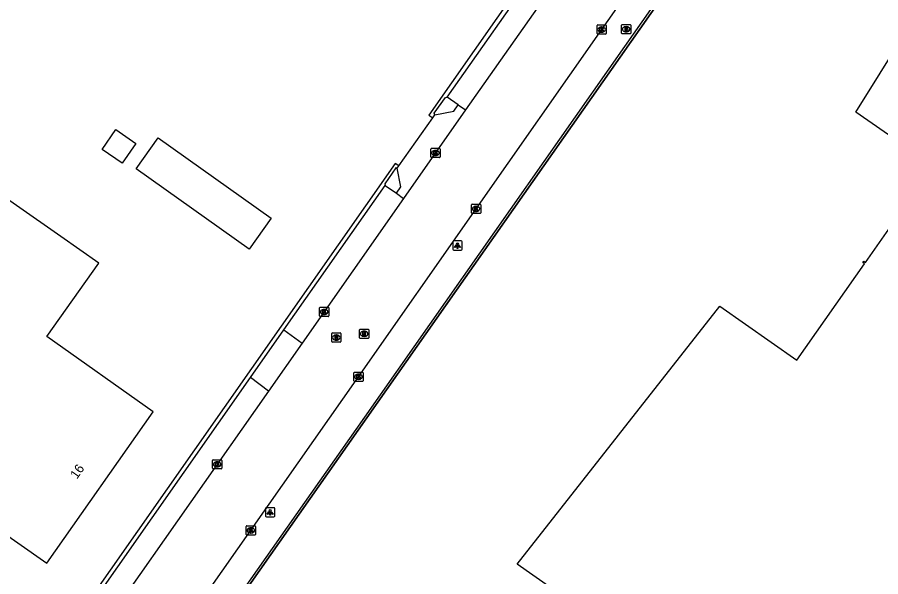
# Model space of a CAD drawing. Extents: x 155018 to 156648, y 383980 to 385733.
# Drawn here: x 155571.4 to 155664.5, y 384753.9 to 384814.2 of the extents above; entities that cross this region are included whole.
import ezdxf

# ---------------------------------------------------------------- set-up
doc = ezdxf.new("R2010")
doc.units = 0
for name, color, linetype in [('IMGEO_Brandkraan', 7, 'Continuous'), ('IMGEO_Groenvoorziening', 7, 'Continuous'), ('IMGEO_Hek', 7, 'Continuous'), ('IMGEO_Kolk', 7, 'Continuous'), ('IMGEO_Lichtpunt', 7, 'Continuous'), ('IMGEO_Pand', 7, 'Continuous'), ('IMGEO_Pand_nummerreeks', 7, 'Continuous'), ('IMGEO_Parkeervlak_open', 7, 'Continuous'), ('IMGEO_Rijbaan_lokaal_gesloten', 7, 'Continuous'), ('IMGEO_Rioolput', 7, 'Continuous'), ('IMGEO_Voetpad_open', 7, 'Continuous')]:
    doc.layers.add(name, color=color, linetype=linetype)

msp = doc.modelspace()

# ---------------------------------------------------------------- linework, layer by layer
at = {"layer": 'IMGEO_Brandkraan'}
for p, q in [((155636.527, 384812.529), (155636.527, 384813.381)), ((155636.602, 384813.455), (155637.454, 384813.455)), ((155637.015, 384813.235), (155637.04, 384813.235)), ((155637.528, 384813.381), (155637.528, 384812.529)), ((155637.454, 384812.455), (155636.602, 384812.455)), ((155637.038, 384812.675), (155637.013, 384812.675))]:
    msp.add_line(p, q, dxfattribs=at)
for points in [[(155636.527, 384812.529), (155636.527, 384813.381)], [(155636.602, 384813.455), (155637.454, 384813.455)], [(155636.875, 384813.155), (155636.875, 384812.755), (155637.088, 384812.755)], [(155637.106, 384813.155), (155636.875, 384813.155)], [(155637.054, 384813.074), (155637, 384813.074), (155637, 384812.998)], [(155637, 384812.998), (155637.053, 384812.998)], [(155637.062, 384812.922), (155637, 384812.922), (155637, 384812.841)], [(155637, 384812.841), (155637.062, 384812.841)], [(155637.528, 384813.381), (155637.528, 384812.529)], [(155637.454, 384812.455), (155636.602, 384812.455)]]:
    msp.add_lwpolyline(points, dxfattribs=at)
for centre, radius, start, end in [((155636.604, 384813.379), 0.0765, 91.55205, 178.44795), ((155636.604, 384813.379), 0.0765, 91.55205, 178.44795), ((155637.055, 384813.036), 0.0379, 267.82845, 90.93552), ((155637.063, 384812.881), 0.0404, 269.87594, 90.50774), ((155637.094, 384813.006), 0.251, 268.66757, 293.53466), ((155637.11, 384813.01), 0.145, 59.4692, 91.53667), ((155637.135, 384813.057), 0.0922, 285.51372, 58.15012), ((155637.14, 384812.865), 0.105, 301.31148, 78.98903), ((155637.452, 384813.379), 0.0765, 1.55205, 88.44795), ((155637.452, 384813.379), 0.0765, 1.55205, 88.44795), ((155636.604, 384812.531), 0.0765, 181.55205, 268.44795), ((155636.604, 384812.531), 0.0765, 181.55205, 268.44795), ((155637.452, 384812.531), 0.0765, 271.55205, 358.44795), ((155637.452, 384812.531), 0.0765, 271.55205, 358.44795)]:
    msp.add_arc(centre, radius, start, end, dxfattribs=at)
for centre, major_axis, ratio, start_param, end_param in [((155637.014, 384812.955), (-0.387, 0.002), 0.722429, 4.712389, 7.853982), ((155637.039, 384812.955), (-0.39, 0.002), 0.717154, 1.570796, 4.712389)]:
    msp.add_ellipse(centre, major_axis=major_axis, ratio=ratio, start_param=start_param, end_param=end_param, dxfattribs=at)
at = {"layer": 'IMGEO_Groenvoorziening'}
msp.add_lwpolyline([(155669.497, 384856.797), (155669.212, 384856.331), (155667.198, 384853.508), (155667.02, 384853.625), (155588.106, 384741.158), (155588.217, 384741.112), (155586.789, 384739.087), (155582.631, 384733.19), (155582.416, 384732.885), (155582.316, 384732.95)], dxfattribs=at)
at = {"layer": 'IMGEO_Hek'}
msp.add_lwpolyline([(155586.789, 384739.087), (155588.217, 384741.112), (155588.106, 384741.158), (155667.02, 384853.625), (155667.198, 384853.508), (155669.212, 384856.331)], dxfattribs=at)
at = {"layer": 'IMGEO_Kolk'}
for p, q in [((155633.888, 384812.493), (155633.888, 384813.345)), ((155633.963, 384813.419), (155634.815, 384813.419)), ((155634.376, 384813.199), (155634.401, 384813.199)), ((155634.889, 384813.345), (155634.889, 384812.493)), ((155634.815, 384812.419), (155633.963, 384812.419)), ((155634.399, 384812.639), (155634.374, 384812.639)), ((155615.977, 384799.176), (155615.977, 384800.028)), ((155616.052, 384800.102), (155616.904, 384800.102)), ((155616.465, 384799.882), (155616.49, 384799.882)), ((155616.978, 384800.028), (155616.978, 384799.176)), ((155616.904, 384799.102), (155616.052, 384799.102)), ((155616.488, 384799.322), (155616.463, 384799.322)), ((155620.345, 384793.143), (155620.345, 384793.995)), ((155620.42, 384794.069), (155621.272, 384794.069)), ((155620.856, 384793.289), (155620.831, 384793.289)), ((155620.833, 384793.849), (155620.858, 384793.849)), ((155621.346, 384793.995), (155621.346, 384793.143)), ((155621.272, 384793.069), (155620.42, 384793.069)), ((155603.961, 384782.021), (155603.961, 384782.873)), ((155604.036, 384782.947), (155604.888, 384782.947)), ((155604.472, 384782.167), (155604.447, 384782.167)), ((155604.449, 384782.727), (155604.474, 384782.727)), ((155604.962, 384782.873), (155604.962, 384782.021)), ((155604.888, 384781.947), (155604.036, 384781.947)), ((155607.671, 384775.025), (155607.671, 384775.877)), ((155607.746, 384775.951), (155608.598, 384775.951)), ((155608.159, 384775.731), (155608.184, 384775.731)), ((155608.672, 384775.877), (155608.672, 384775.025)), ((155608.598, 384774.951), (155607.746, 384774.951)), ((155608.182, 384775.171), (155608.157, 384775.171)), ((155592.434, 384765.572), (155592.434, 384766.424)), ((155592.509, 384766.498), (155593.361, 384766.498)), ((155592.922, 384766.278), (155592.947, 384766.278)), ((155593.435, 384766.424), (155593.435, 384765.572)), ((155593.361, 384765.498), (155592.509, 384765.498)), ((155592.945, 384765.718), (155592.92, 384765.718)), ((155596.054, 384758.444), (155596.054, 384759.296)), ((155596.129, 384759.37), (155596.981, 384759.37)), ((155596.542, 384759.15), (155596.567, 384759.15)), ((155597.055, 384759.296), (155597.055, 384758.444)), ((155596.981, 384758.37), (155596.129, 384758.37)), ((155596.565, 384758.59), (155596.54, 384758.59))]:
    msp.add_line(p, q, dxfattribs=at)
for points in [[(155633.888, 384812.493), (155633.888, 384813.345)], [(155633.963, 384813.419), (155634.815, 384813.419)], [(155634.209, 384813.119), (155634.332, 384813.119), (155634.332, 384812.968), (155634.462, 384813.119), (155634.626, 384813.119), (155634.48, 384812.968), (155634.633, 384812.719), (155634.481, 384812.719), (155634.396, 384812.883), (155634.332, 384812.816), (155634.332, 384812.719), (155634.209, 384812.719), (155634.209, 384813.119)], [(155634.889, 384813.345), (155634.889, 384812.493)], [(155634.815, 384812.419), (155633.963, 384812.419)], [(155615.977, 384799.176), (155615.977, 384800.028)], [(155616.052, 384800.102), (155616.904, 384800.102)], [(155616.298, 384799.802), (155616.421, 384799.802), (155616.421, 384799.651), (155616.551, 384799.802), (155616.715, 384799.802), (155616.569, 384799.651), (155616.722, 384799.402), (155616.57, 384799.402), (155616.485, 384799.566), (155616.421, 384799.499), (155616.421, 384799.402), (155616.298, 384799.402), (155616.298, 384799.802)], [(155616.978, 384800.028), (155616.978, 384799.176)], [(155616.904, 384799.102), (155616.052, 384799.102)], [(155620.345, 384793.143), (155620.345, 384793.995)], [(155620.42, 384794.069), (155621.272, 384794.069)], [(155620.666, 384793.769), (155620.789, 384793.769), (155620.789, 384793.618), (155620.919, 384793.769), (155621.083, 384793.769), (155620.937, 384793.618), (155621.09, 384793.369), (155620.938, 384793.369), (155620.853, 384793.533), (155620.789, 384793.466), (155620.789, 384793.369), (155620.666, 384793.369), (155620.666, 384793.769)], [(155621.346, 384793.995), (155621.346, 384793.143)], [(155621.272, 384793.069), (155620.42, 384793.069)], [(155603.961, 384782.021), (155603.961, 384782.873)], [(155604.036, 384782.947), (155604.888, 384782.947)], [(155604.282, 384782.647), (155604.405, 384782.647), (155604.405, 384782.496), (155604.535, 384782.647), (155604.699, 384782.647), (155604.553, 384782.496), (155604.706, 384782.247), (155604.554, 384782.247), (155604.469, 384782.411), (155604.405, 384782.344), (155604.405, 384782.247), (155604.282, 384782.247), (155604.282, 384782.647)], [(155604.962, 384782.873), (155604.962, 384782.021)], [(155604.888, 384781.947), (155604.036, 384781.947)], [(155607.671, 384775.025), (155607.671, 384775.877)], [(155607.746, 384775.951), (155608.598, 384775.951)], [(155607.992, 384775.651), (155608.115, 384775.651), (155608.115, 384775.5), (155608.245, 384775.651), (155608.409, 384775.651), (155608.263, 384775.5), (155608.416, 384775.251), (155608.264, 384775.251), (155608.179, 384775.415), (155608.115, 384775.348), (155608.115, 384775.251), (155607.992, 384775.251), (155607.992, 384775.651)], [(155608.672, 384775.877), (155608.672, 384775.025)], [(155608.598, 384774.951), (155607.746, 384774.951)], [(155592.434, 384765.572), (155592.434, 384766.424)], [(155592.509, 384766.498), (155593.361, 384766.498)], [(155593.435, 384766.424), (155593.435, 384765.572)], [(155593.361, 384765.498), (155592.509, 384765.498)], [(155592.755, 384766.198), (155592.878, 384766.198), (155592.878, 384766.047), (155593.008, 384766.198), (155593.172, 384766.198), (155593.026, 384766.047), (155593.179, 384765.798), (155593.027, 384765.798), (155592.942, 384765.962), (155592.878, 384765.895), (155592.878, 384765.798), (155592.755, 384765.798), (155592.755, 384766.198)], [(155596.054, 384758.444), (155596.054, 384759.296)], [(155596.129, 384759.37), (155596.981, 384759.37)], [(155596.375, 384759.07), (155596.498, 384759.07), (155596.498, 384758.919), (155596.628, 384759.07), (155596.792, 384759.07), (155596.646, 384758.919), (155596.799, 384758.67), (155596.647, 384758.67), (155596.562, 384758.834), (155596.498, 384758.767), (155596.498, 384758.67), (155596.375, 384758.67), (155596.375, 384759.07)], [(155597.055, 384759.296), (155597.055, 384758.444)], [(155596.981, 384758.37), (155596.129, 384758.37)]]:
    msp.add_lwpolyline(points, dxfattribs=at)
for centre, start, end in [((155633.965, 384813.343), 91.55205, 178.44795), ((155633.965, 384813.343), 91.55205, 178.44795), ((155634.813, 384813.343), 1.55205, 88.44795), ((155634.813, 384813.343), 1.55205, 88.44795), ((155633.965, 384812.495), 181.55205, 268.44795), ((155633.965, 384812.495), 181.55205, 268.44795), ((155634.813, 384812.495), 271.55205, 358.44795), ((155634.813, 384812.495), 271.55205, 358.44795), ((155616.054, 384800.026), 91.55205, 178.44795), ((155616.054, 384800.026), 91.55205, 178.44795), ((155616.902, 384800.026), 1.55205, 88.44795), ((155616.902, 384800.026), 1.55205, 88.44795), ((155616.054, 384799.178), 181.55205, 268.44795), ((155616.054, 384799.178), 181.55205, 268.44795), ((155616.902, 384799.178), 271.55205, 358.44795), ((155616.902, 384799.178), 271.55205, 358.44795), ((155620.422, 384793.993), 91.55205, 178.44795), ((155620.422, 384793.993), 91.55205, 178.44795), ((155621.27, 384793.993), 1.55205, 88.44795), ((155621.27, 384793.993), 1.55205, 88.44795), ((155620.422, 384793.145), 181.55205, 268.44795), ((155620.422, 384793.145), 181.55205, 268.44795), ((155621.27, 384793.145), 271.55205, 358.44795), ((155621.27, 384793.145), 271.55205, 358.44795), ((155604.038, 384782.871), 91.55205, 178.44795), ((155604.038, 384782.871), 91.55205, 178.44795), ((155604.886, 384782.871), 1.55205, 88.44795), ((155604.886, 384782.871), 1.55205, 88.44795), ((155604.038, 384782.023), 181.55205, 268.44795), ((155604.038, 384782.023), 181.55205, 268.44795), ((155604.886, 384782.023), 271.55205, 358.44795), ((155604.886, 384782.023), 271.55205, 358.44795), ((155607.748, 384775.875), 91.55205, 178.44795), ((155607.748, 384775.875), 91.55205, 178.44795), ((155608.596, 384775.875), 1.55205, 88.44795), ((155608.596, 384775.875), 1.55205, 88.44795), ((155607.748, 384775.027), 181.55205, 268.44795), ((155607.748, 384775.027), 181.55205, 268.44795), ((155608.596, 384775.027), 271.55205, 358.44795), ((155608.596, 384775.027), 271.55205, 358.44795), ((155592.511, 384766.422), 91.55205, 178.44795), ((155592.511, 384766.422), 91.55205, 178.44795), ((155593.359, 384766.422), 1.55205, 88.44795), ((155593.359, 384766.422), 1.55205, 88.44795), ((155592.511, 384765.574), 181.55205, 268.44795), ((155592.511, 384765.574), 181.55205, 268.44795), ((155593.359, 384765.574), 271.55205, 358.44795), ((155593.359, 384765.574), 271.55205, 358.44795), ((155596.131, 384759.294), 91.55205, 178.44795), ((155596.131, 384759.294), 91.55205, 178.44795), ((155596.979, 384759.294), 1.55205, 88.44795), ((155596.979, 384759.294), 1.55205, 88.44795), ((155596.131, 384758.446), 181.55205, 268.44795), ((155596.131, 384758.446), 181.55205, 268.44795), ((155596.979, 384758.446), 271.55205, 358.44795), ((155596.979, 384758.446), 271.55205, 358.44795)]:
    msp.add_arc(centre, 0.0765, start, end, dxfattribs=at)
for centre, major_axis, ratio, start_param, end_param in [((155634.375, 384812.919), (-0.387, 0.002), 0.722429, 4.712389, 7.853982), ((155634.4, 384812.919), (-0.39, 0.002), 0.717154, 1.570796, 4.712389), ((155616.464, 384799.602), (-0.387, 0.002), 0.722429, 4.712389, 7.853982), ((155616.489, 384799.602), (-0.39, 0.002), 0.717154, 1.570796, 4.712389), ((155620.832, 384793.569), (-0.387, 0.002), 0.722429, 4.712389, 7.853982), ((155620.857, 384793.569), (-0.39, 0.002), 0.717154, 1.570796, 4.712389), ((155604.448, 384782.447), (-0.387, 0.002), 0.722429, 4.712389, 7.853982), ((155604.473, 384782.447), (-0.39, 0.002), 0.717154, 1.570796, 4.712389), ((155608.158, 384775.451), (-0.387, 0.002), 0.722429, 4.712389, 7.853982), ((155608.183, 384775.451), (-0.39, 0.002), 0.717154, 1.570796, 4.712389), ((155592.921, 384765.998), (-0.387, 0.002), 0.722429, 4.712389, 7.853982), ((155592.946, 384765.998), (-0.39, 0.002), 0.717154, 1.570796, 4.712389), ((155596.541, 384758.87), (-0.387, 0.002), 0.722429, 4.712389, 7.853982), ((155596.566, 384758.87), (-0.39, 0.002), 0.717154, 1.570796, 4.712389)]:
    msp.add_ellipse(centre, major_axis=major_axis, ratio=ratio, start_param=start_param, end_param=end_param, dxfattribs=at)
at = {"layer": 'IMGEO_Lichtpunt'}
for p, q in [((155618.344, 384790.011), (155618.344, 384789.204)), ((155618.344, 384790.011), (155618.344, 384789.204)), ((155619.246, 384790.106), (155618.438, 384790.106)), ((155619.246, 384790.106), (155618.438, 384790.106)), ((155619.34, 384789.204), (155619.34, 384790.011)), ((155619.34, 384789.204), (155619.34, 384790.011)), ((155618.438, 384789.11), (155619.246, 384789.11)), ((155618.438, 384789.11), (155619.246, 384789.11)), ((155598.142, 384761.23), (155598.142, 384760.423)), ((155598.142, 384761.23), (155598.142, 384760.423)), ((155599.044, 384761.325), (155598.236, 384761.325)), ((155599.044, 384761.325), (155598.236, 384761.325)), ((155599.138, 384760.423), (155599.138, 384761.23)), ((155599.138, 384760.423), (155599.138, 384761.23)), ((155598.236, 384760.329), (155599.044, 384760.329)), ((155598.236, 384760.329), (155599.044, 384760.329))]:
    msp.add_line(p, q, dxfattribs=at)
for points in [[(155618.718, 384789.675), (155618.757, 384789.647), (155618.569, 384789.385), (155618.531, 384789.412), (155618.718, 384789.675)], [(155618.82, 384789.627), (155618.867, 384789.627), (155618.867, 384789.305), (155618.82, 384789.305), (155618.82, 384789.627)], [(155618.93, 384789.647), (155618.968, 384789.674), (155619.155, 384789.412), (155619.116, 384789.384), (155618.93, 384789.647)], [(155598.516, 384760.894), (155598.555, 384760.866), (155598.367, 384760.604), (155598.329, 384760.631), (155598.516, 384760.894)], [(155598.618, 384760.846), (155598.665, 384760.846), (155598.665, 384760.524), (155598.618, 384760.524), (155598.618, 384760.846)], [(155598.728, 384760.866), (155598.766, 384760.893), (155598.953, 384760.631), (155598.914, 384760.603), (155598.728, 384760.866)]]:
    msp.add_lwpolyline(points, dxfattribs=at)
for centre in [(155618.843, 384789.809), (155598.641, 384761.028)]:
    msp.add_circle(centre, 0.0994, dxfattribs=at)
for centre, start, end in [((155618.438, 384790.011), 90, 180), ((155618.438, 384790.011), 90, 180), ((155619.246, 384790.011), 0, 90), ((155619.246, 384790.011), 0, 90), ((155618.438, 384789.204), 180, 270), ((155618.438, 384789.204), 180, 270), ((155619.246, 384789.204), 270, 0), ((155619.246, 384789.204), 270, 360), ((155598.236, 384761.23), 90, 180), ((155598.236, 384761.23), 90, 180), ((155599.044, 384761.23), 0, 90), ((155599.044, 384761.23), 0, 90), ((155598.236, 384760.423), 180, 270), ((155598.236, 384760.423), 180, 270), ((155599.044, 384760.423), 270, 0), ((155599.044, 384760.423), 270, 360)]:
    msp.add_arc(centre, 0.0946, start, end, dxfattribs=at)
at = {"layer": 'IMGEO_Pand'}
for points in [[(155711.841, 384668.122), (155622.681, 384730.542), (155635.158, 384748.297), (155625.281, 384755.221), (155647.138, 384783.07), (155655.452, 384777.248), (155662.738, 384787.65), (155662.546, 384787.778), (155662.649, 384787.925), (155662.832, 384787.785), (155670.123, 384798.196), (155661.809, 384804.018), (155680.521, 384834.071)], [(155527.932, 384782.896), (155556.634, 384762.863), (155560.734, 384760.001), (155563.08, 384763.359), (155574.573, 384755.332), (155586.015, 384771.676), (155574.557, 384779.779), (155580.154, 384787.72), (155576.058, 384790.588), (155547.35, 384810.655), (155527.932, 384782.896)], [(155582.019, 384802.119), (155584.172, 384800.619), (155582.678, 384798.516), (155580.541, 384799.974), (155582.019, 384802.119)], [(155586.573, 384801.243), (155598.747, 384792.566), (155596.367, 384789.227), (155584.193, 384797.904), (155586.573, 384801.243)]]:
    msp.add_lwpolyline(points, dxfattribs=at)
at = {"layer": 'IMGEO_Parkeervlak_open'}
for points in [[(155618.908, 384804.799), (155617.739, 384805.63)], [(155611.036, 384796.09), (155612.249, 384795.277)]]:
    msp.add_lwpolyline(points, dxfattribs=at)
at = {"layer": 'IMGEO_Rijbaan_lokaal_gesloten'}
for points in [[(155586.289, 384744.214), (155590.343, 384750), (155608.173, 384775.45), (155620.847, 384793.568), (155634.39, 384812.919), (155647.778, 384831.987), (155658, 384846.57), (155663.285, 384854.104), (155665.547, 384857.446), (155665.874, 384857.967)], [(155652.394, 384850.88), (155629.679, 384818.438), (155619.716, 384804.252)], [(155619.716, 384804.252), (155613.015, 384794.672)], [(155613.015, 384794.672), (155602.107, 384779.088)], [(155602.107, 384779.088), (155598.478, 384773.909)], [(155598.478, 384773.909), (155581.725, 384750), (155573.395, 384738.09)]]:
    msp.add_lwpolyline(points, dxfattribs=at)
at = {"layer": 'IMGEO_Rioolput'}
for p, q in [((155608.277, 384779.659), (155608.277, 384780.511)), ((155608.352, 384780.585), (155609.204, 384780.585)), ((155608.765, 384780.365), (155608.79, 384780.365)), ((155609.278, 384780.511), (155609.278, 384779.659)), ((155605.276, 384779.259), (155605.276, 384780.111)), ((155605.351, 384780.185), (155606.203, 384780.185)), ((155605.787, 384779.405), (155605.762, 384779.405)), ((155605.764, 384779.965), (155605.789, 384779.965)), ((155606.277, 384780.111), (155606.277, 384779.259)), ((155609.204, 384779.585), (155608.352, 384779.585)), ((155608.788, 384779.805), (155608.763, 384779.805)), ((155606.203, 384779.185), (155605.351, 384779.185))]:
    msp.add_line(p, q, dxfattribs=at)
for points in [[(155608.277, 384779.659), (155608.277, 384780.511)], [(155608.352, 384780.585), (155609.204, 384780.585)], [(155608.866, 384780.283), (155608.614, 384780.285), (155608.614, 384779.885)], [(155608.792, 384780.204), (155608.738, 384780.204), (155608.738, 384780.123)], [(155609.278, 384780.511), (155609.278, 384779.659)], [(155605.276, 384779.259), (155605.276, 384780.111)], [(155605.351, 384780.185), (155606.203, 384780.185)], [(155605.865, 384779.883), (155605.613, 384779.885), (155605.613, 384779.485)], [(155605.613, 384779.485), (155605.737, 384779.485), (155605.737, 384779.647), (155605.748, 384779.647)], [(155605.791, 384779.804), (155605.737, 384779.804), (155605.737, 384779.723)], [(155605.737, 384779.723), (155605.789, 384779.723)], [(155605.795, 384779.618), (155605.866, 384779.485), (155606.006, 384779.485), (155605.941, 384779.611)], [(155606.277, 384780.111), (155606.277, 384779.259)], [(155609.204, 384779.585), (155608.352, 384779.585)], [(155608.614, 384779.885), (155608.738, 384779.885), (155608.738, 384780.047), (155608.749, 384780.047)], [(155608.738, 384780.123), (155608.79, 384780.123)], [(155608.796, 384780.018), (155608.867, 384779.885), (155609.007, 384779.885), (155608.942, 384780.011)], [(155606.203, 384779.185), (155605.351, 384779.185)]]:
    msp.add_lwpolyline(points, dxfattribs=at)
for centre, radius, start, end in [((155608.354, 384780.509), 0.0765, 91.55205, 178.44795), ((155608.354, 384780.509), 0.0765, 91.55205, 178.44795), ((155608.798, 384780.108), 0.0964, 77.00612, 93.18647), ((155608.812, 384780.165), 0.0378, 276.66336, 79.67722), ((155608.865, 384780.173), 0.109, 350.36119, 89.41601), ((155609.202, 384780.509), 0.0765, 1.55205, 88.44795), ((155609.202, 384780.509), 0.0765, 1.55205, 88.44795), ((155605.353, 384780.109), 0.0765, 91.55205, 178.44795), ((155605.353, 384780.109), 0.0765, 91.55205, 178.44795), ((155605.353, 384779.261), 0.0765, 181.55205, 268.44795), ((155605.353, 384779.261), 0.0765, 181.55205, 268.44795), ((155605.747, 384779.594), 0.0533, 26.02933, 88.69889), ((155605.773, 384779.912), 0.19, 274.7715, 282.96867), ((155605.797, 384779.708), 0.0964, 77.00612, 93.18647), ((155605.811, 384779.765), 0.0378, 276.66336, 79.67722), ((155605.864, 384779.773), 0.109, 350.36119, 89.41601), ((155605.862, 384779.773), 0.112, 277.58423, 350.98172), ((155605.846, 384779.558), 0.108, 29.51342, 73.79051), ((155606.201, 384780.109), 0.0765, 1.55205, 88.44795), ((155606.201, 384780.109), 0.0765, 1.55205, 88.44795), ((155606.201, 384779.261), 0.0765, 271.55205, 358.44795), ((155606.201, 384779.261), 0.0765, 271.55205, 358.44795), ((155608.354, 384779.661), 0.0765, 181.55205, 268.44795), ((155608.354, 384779.661), 0.0765, 181.55205, 268.44795), ((155608.748, 384779.994), 0.0533, 26.02933, 88.69889), ((155608.774, 384780.312), 0.19, 274.7715, 282.96867), ((155608.863, 384780.173), 0.112, 277.58423, 350.98172), ((155608.847, 384779.958), 0.108, 29.51342, 73.79051), ((155609.202, 384779.661), 0.0765, 271.55205, 358.44795), ((155609.202, 384779.661), 0.0765, 271.55205, 358.44795)]:
    msp.add_arc(centre, radius, start, end, dxfattribs=at)
for centre, major_axis, ratio, start_param, end_param in [((155608.764, 384780.085), (-0.387, 0.002), 0.722429, 4.712389, 7.853982), ((155608.789, 384780.085), (-0.39, 0.002), 0.717154, 1.570796, 4.712389), ((155605.763, 384779.685), (-0.387, 0.002), 0.722429, 4.712389, 7.853982), ((155605.788, 384779.685), (-0.39, 0.002), 0.717154, 1.570796, 4.712389)]:
    msp.add_ellipse(centre, major_axis=major_axis, ratio=ratio, start_param=start_param, end_param=end_param, dxfattribs=at)
at = {"layer": 'IMGEO_Voetpad_open'}
for points in [[(155668.817, 384856.954), (155660.389, 384844.659), (155636.862, 384811.074), (155608.808, 384771.107), (155594.019, 384750), (155586.655, 384739.49)], [(155649.247, 384851.98), (155649.459, 384851.832), (155615.737, 384803.696), (155616.168, 384803.406)], [(155617.739, 384805.63), (155627.894, 384820.122), (155649.878, 384851.473)], [(155616.394, 384803.727), (155616.33, 384803.906), (155617.539, 384805.599), (155617.739, 384805.63)], [(155616.394, 384803.727), (155618.447, 384804.097), (155618.908, 384804.799)], [(155618.908, 384804.799), (155619.716, 384804.252)], [(155616.168, 384803.406), (155616.394, 384803.727)], [(155612.508, 384798.198), (155616.168, 384803.406)], [(155612.508, 384798.198), (155612.129, 384798.458), (155578.198, 384750), (155566.056, 384732.66), (155553.747, 384715.183), (155553.739, 384715.172)], [(155612.346, 384797.968), (155612.196, 384797.988), (155611.005, 384796.282), (155611.036, 384796.09)], [(155612.249, 384795.277), (155612.719, 384795.936), (155612.346, 384797.968)], [(155612.346, 384797.968), (155612.508, 384798.198)], [(155600.119, 384780.503), (155611.036, 384796.09)], [(155612.249, 384795.277), (155613.015, 384794.672)], [(155596.516, 384775.358), (155600.119, 384780.503)], [(155600.119, 384780.503), (155602.107, 384779.088)], [(155571.397, 384739.494), (155578.755, 384750), (155596.516, 384775.358)], [(155598.478, 384773.909), (155596.516, 384775.358)]]:
    msp.add_lwpolyline(points, dxfattribs=at)

# ---------------------------------------------------------------- texts
at = {"layer": 'IMGEO_Pand_nummerreeks'}
msp.add_text('16', height=1, rotation=55.00516, dxfattribs=at).set_placement((155577.808, 384764.347))

doc.saveas('drawing.dxf')
